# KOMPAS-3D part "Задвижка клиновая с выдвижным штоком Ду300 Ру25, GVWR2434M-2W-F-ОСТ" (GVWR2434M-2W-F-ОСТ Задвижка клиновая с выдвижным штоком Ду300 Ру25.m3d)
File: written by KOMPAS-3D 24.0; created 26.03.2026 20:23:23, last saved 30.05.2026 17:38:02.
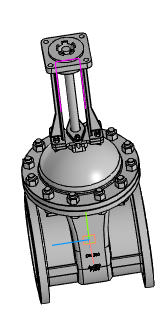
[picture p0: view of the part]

Document properties: Автор: R2D2; Полное имя файла: E:\Работа\Зайцев\GVWR2434M-2W-F-ОСТ Задвижка клиновая с выдвижным штоком DN.ru Ду50-300 Ру25\исходные материалы\DN300\GVWR2434M-2W-F-ОСТ Задвижка клиновая с выдвижным штоком Ду300 Ру25.m3d

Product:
- Component [detail]: AS 1110 - M10 x 35  | qty 4  | pos. 2  | Комментарий: Болты и винты   шестигранные точные   метрические ISO; Автор: R2D2; additional columns: Сталь, мягкая; source file: AS 1110 - M10 x 35 AS 1110 - M10 x 35.m3d
- Component [detail]: ANSI B18.2.4.2M - M10x1,5 - 16  | designation ANSI B18.2.4.2M - M10x1,5  | qty 4  | pos. 3  | Комментарий: Типы метрических   шестигранных гаек   2; Автор: R2D2; additional columns: Сталь, мягкая; source file: ANSI B18.2.4.2M - M10x1,5 ANSI B18.2.4.2M - M10x1,5 - 16.m3d
- Component [detail]: ANSI B18.2.4.2M - M8x1,25 - 13  | designation ANSI B18.2.4.2M - M8x1,25  | qty 1  | pos. 4  | Комментарий: Типы метрических   шестигранных гаек   2; Автор: R2D2; additional columns: Сталь, мягкая; source file: ANSI B18.2.4.2M - M8x1,25 ANSI B18.2.4.2M - M8x1,25 - 13.m3d
- Component [detail]: ANSI B18.2.4.2M - M20x2,5 - 30  | designation ANSI B18.2.4.2M - M20x2,5  | qty 12  | pos. 5  | Комментарий: Типы метрических   шестигранных гаек   2; Автор: R2D2; additional columns: Сталь, мягкая; source file: ANSI B18.2.4.2M - M20x2,5 ANSI B18.2.4.2M - M20x2,5 - 30.m3d
- Component [detail]: AS 1110 - M20 x 70  | qty 12  | pos. 6  | Комментарий: Болты и винты   шестигранные точные   метрические ISO; Автор: R2D2; additional columns: Сталь, мягкая; source file: AS 1110 - M20 x 70 AS 1110 - M20 x 70.m3d
- Component [detail]: Деталь1  | qty 1  | pos. 7  | Автор: R2D2; additional columns: Типовые; source file: 2.m3d
- Component [detail]: ANSI B18.2.4.2M - M8x1,25 - 13  | designation ANSI B18.2.4.2M - M8x1,25-01  | qty 1  | pos. 8  | Комментарий: Типы метрических   шестигранных гаек   2; Автор: R2D2; additional columns: Сталь, мягкая; source file: ANSI B18.2.4.2M - M8x1,25 ANSI B18.2.4.2M - M8x1,25 - 13.m3d
- Component [detail]: Фланец  | qty 2  | pos. 7  | Автор: R2D2; additional columns: Типовые; source file: Фланец DN300 Pn25 b40.m3d
- Component [detail]: Деталь1  | qty 1  | pos. 9  | Автор: R2D2; additional columns: Типовые; source file: Фланец В.m3d
- Body: Тело 1  | qty 1
    Масса: 559.952517
- Body: Тело 2  | qty 1
    Масса: 559.952517
- Part/product: Задвижка клиновая с выдвижным штоком Ду300 Ру25  | designation GVWR2434M-2W-F-ОСТ
    Масса: 265
    Раздел спецификации: Прочие изделия
    Примечание: D040-07592

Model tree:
1. Массив по концентрической сетке:1  (labels: Грань.Твердое тело1)  (12 pattern instances)
     Шаг 2 = 360
2. Массив по сетке:1  (labels: Грань.Твердое тело1)  (4 pattern instances)
     Шаг 1 = 50; Угол раствора = 90; Шаг 2 = 120
3. Масштабирование:1
4. Масштабирование : Твердое тело1
5. Масштабирование : Solid1  (labels: Твердое тело1; Solid1)
     Масштаб по оси Х = 1; Масштаб по оси Y = 1; Масштаб по оси Z = 1; Коэффициент = 1.5
6. Эскиз:1  (with: Вершина.Элемент выдавливания:2)
7. Элемент по траектории:1  (with: Грань.Элемент выдавливания:2)
     Длина траектории = 679.228
8. Элемент выдавливания:1  (with: Грань.Элемент по траектории:1, Грань.Элемент вращения:1)
     Расстояние 1 = 21.6625
9. Элемент выдавливания:2  (with: Грань.Элемент по траектории:1, Грань.Элемент вращения:1)
     Расстояние 1 = 11.3947
10. Скругление:1  (with: Ребро.Элемент выдавливания:2, Ребро.Элемент выдавливания:1)
     Радиус = 10
11. Элемент выдавливания:3  (with: Грань.Элемент по траектории:1)
     Расстояние 1 = 354.258
12. Эскиз:2  (with: Ребро.Элемент выдавливания:2)
13. Элемент вращения:1
     Угол 1 = 360
14. Зеркальный массив:1
15. Экземпляр ( 1 )
16. Экземпляр ( 2 )  (with: Элемент вращения:1)
17. Фаска:1  (with: Ребро.Элемент вращения:1)  (labels: Ребро.Элемент вращения:1.Экземпляр ( 2 ))
     Угол = 45; Длина 1 = 4; Длина 2 = 4
18. Эскиз:3
19. Элемент выдавливания:4  (with: Грань.Элемент по траектории:1, Грань.Элемент вращения:1, Грань.Элемент выдавливания:1, Грань.Элемент выдавливания:2, Грань.Элемент выдавливания:4)  (labels: Грань.Твердое тело1; Грань.Solid1; Solid1; Твердое тело1)
     Расстояние 1 = 188.5; Смещение 1 = 1; Ориентация = 2; Расстояние = -250; Ориентация = 2; Расстояние = -1100

Expressions: 375+8
Referenced files in E:\Работа\Зайцев\GVWR2434M-2W-F-ОСТ Задвижка клиновая с выдвижным штоком DN.ru Ду50-300 Ру25\исходные материалы\DN300\: AS 1110 - M10 x 35 AS 1110 - M10 x 35.m3d, ANSI B18.2.4.2M - M10x1,5 ANSI B18.2.4.2M - M10x1,5 - 16.m3d, ANSI B18.2.4.2M - M8x1,25 ANSI B18.2.4.2M - M8x1,25 - 13.m3d, ANSI B18.2.4.2M - M20x2,5 ANSI B18.2.4.2M - M20x2,5 - 30.m3d, AS 1110 - M20 x 70 AS 1110 - M20 x 70.m3d, 2.m3d, Фланец DN300 Pn25 b40.m3d, Фланец В.m3d
Referenced files in E:\Работа\Зайцев\GVWR3131M-2W-F-S Задвижка клиновая с выдвижным штоком DN.ru Ду50-200 Ру63\DN200\исходные материалы\: ANSI B18.2.4.2M - M20x2,5 ANSI B18.2.4.2M - M20x2,5 - 30.m3d, AS 1110 - M20 x 70 AS 1110 - M20 x 70.m3d, ANSI B18.2.4.2M - M10x1,5 ANSI B18.2.4.2M - M10x1,5 - 16.m3d, AS 1110 - M10 x 35 AS 1110 - M10 x 35.m3d
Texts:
  GVWR2434M-2W-F-ОСТ
  Ду300
  GOST 26.020 Pr3
  Ру25
  AS 1110 - M10 x 35 AS 1110 - M10 x 35 (1)
  ANSI B18.2.4.2M - M10x1,5 ANSI B18.2.4.2M - M10x1,5 - 16 (1)
  ANSI B18.2.4.2M - M8x1,25 ANSI B18.2.4.2M - M8x1,25 - 13
  ANSI B18.2.4.2M - M20x2,5 ANSI B18.2.4.2M - M20x2,5 - 30 (1)
  AS 1110 - M20 x 70 AS 1110 - M20 x 70 (1)
  Деталь1 Деталь1
  ANSI B18.2.4.2M - M20x2,5 ANSI B18.2.4.2M - M20x2,5 - 30 (2)
  AS 1110 - M20 x 70 AS 1110 - M20 x 70 (2)
  ANSI B18.2.4.2M - M20x2,5 ANSI B18.2.4.2M - M20x2,5 - 30 (3)
  AS 1110 - M20 x 70 AS 1110 - M20 x 70 (3)
  ANSI B18.2.4.2M - M20x2,5 ANSI B18.2.4.2M - M20x2,5 - 30 (4)
  AS 1110 - M20 x 70 AS 1110 - M20 x 70 (4)
  ANSI B18.2.4.2M - M20x2,5 ANSI B18.2.4.2M - M20x2,5 - 30 (5)
  AS 1110 - M20 x 70 AS 1110 - M20 x 70 (5)
  ANSI B18.2.4.2M - M20x2,5 ANSI B18.2.4.2M - M20x2,5 - 30 (6)
  AS 1110 - M20 x 70 AS 1110 - M20 x 70 (6)
  ANSI B18.2.4.2M - M20x2,5 ANSI B18.2.4.2M - M20x2,5 - 30 (7)
  AS 1110 - M20 x 70 AS 1110 - M20 x 70 (7)
  ANSI B18.2.4.2M - M20x2,5 ANSI B18.2.4.2M - M20x2,5 - 30 (8)
  AS 1110 - M20 x 70 AS 1110 - M20 x 70 (8)
  ANSI B18.2.4.2M - M20x2,5 ANSI B18.2.4.2M - M20x2,5 - 30 (9)
  AS 1110 - M20 x 70 AS 1110 - M20 x 70 (9)
  ANSI B18.2.4.2M - M20x2,5 ANSI B18.2.4.2M - M20x2,5 - 30 (10)
  AS 1110 - M20 x 70 AS 1110 - M20 x 70 (10)
  ANSI B18.2.4.2M - M20x2,5 ANSI B18.2.4.2M - M20x2,5 - 30 (11)
  AS 1110 - M20 x 70 AS 1110 - M20 x 70 (11)
  ANSI B18.2.4.2M - M20x2,5 ANSI B18.2.4.2M - M20x2,5 - 30 (12)
  AS 1110 - M20 x 70 AS 1110 - M20 x 70 (12)
  ANSI B18.2.4.2M - M10x1,5 ANSI B18.2.4.2M - M10x1,5 - 16 (2)
  AS 1110 - M10 x 35 AS 1110 - M10 x 35 (2)
  ANSI B18.2.4.2M - M10x1,5 ANSI B18.2.4.2M - M10x1,5 - 16 (3)
  AS 1110 - M10 x 35 AS 1110 - M10 x 35 (3)
  ANSI B18.2.4.2M - M10x1,5 ANSI B18.2.4.2M - M10x1,5 - 16 (4)
  AS 1110 - M10 x 35 AS 1110 - M10 x 35 (4)
  ANSI B18.2.4.2M - M8x1,25-01 ANSI B18.2.4.2M - M8x1,25 - 13
  Фланец (1)
  Фланец (2)
  Ось Y.Начало координат
  Ось Z.Начало координат
  Плоскость ZY.Начало координат
  Плоскость ZX.Начало координат
  Плоскость XY.Начало координат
